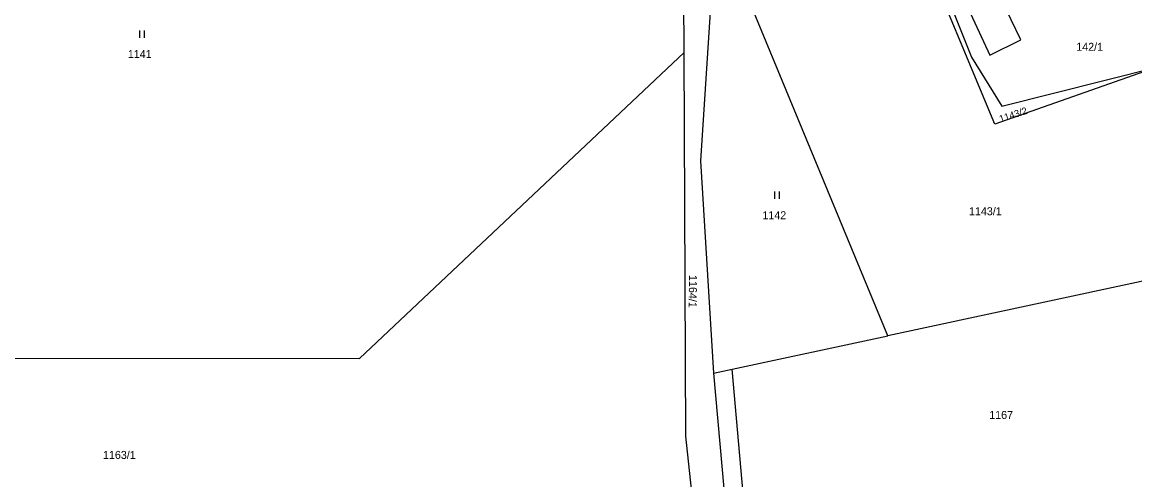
# Model space of a CAD drawing. Extents: x -520431 to -517205, y -1075927 to -1074013.
# Drawn here: x -518114.5 to -517878.1, y -1074275.3 to -1074178 of the extents above; entities that cross this region are included whole.
import ezdxf

# ---------------------------------------------------------------- set-up
doc = ezdxf.new("R2010")
doc.units = 0
for name, color, linetype in [('Hranice parcel', 7, 'Continuous'), ('Parcelní čísla', 7, 'Continuous'), ('Značky kultur', 7, 'Continuous')]:
    doc.layers.add(name, color=color, linetype=linetype)

msp = doc.modelspace()

# ---------------------------------------------------------------- linework, layer by layer
at = {"layer": 'Hranice parcel'}
for p, q in [((-517973.88, -1074184.44), (-517973.95, -1074168.72)), ((-517930.58, -1074244.65), (-517959.87, -1074173.95)), ((-517856.33, -1074228.71), (-517930.58, -1074244.65)), ((-517963.68, -1074251.76), (-517930.58, -1074244.65)), ((-517967.62, -1074252.6), (-517963.68, -1074251.76)), ((-517960.26, -1074290.32), (-517963.68, -1074251.76))]:
    msp.add_line(p, q, dxfattribs=at)
for points in [[(-517873.48, -1074187.52), (-517907.9, -1074199.62), (-517924.26, -1074160.28)], [(-517922.94, -1074159.92), (-517912.81, -1074185.42), (-517906.36, -1074195.86), (-517873.48, -1074187.52)], [(-517916.75, -1074168.08), (-517908.93, -1074185.01), (-517902.33, -1074181.69), (-517910.54, -1074164.66), (-517916.75, -1074168.08)], [(-517961.77, -1074167.62), (-517968.27, -1074174.7), (-517970.39, -1074207.47), (-517967.62, -1074252.6)], [(-518160.31, -1074249.43), (-518042.84, -1074249.49), (-517973.88, -1074184.44)], [(-517969.62, -1074302.45), (-517973.51, -1074266.04), (-517973.88, -1074184.44)], [(-517967.62, -1074252.6), (-517964.09, -1074292.2), (-517962.91, -1074301.55)]]:
    msp.add_lwpolyline(points, dxfattribs=at)
at = {"layer": 'Značky kultur'}
for p, q in [((-518089.51, -1074181.26), (-518089.51, -1074179.76)), ((-518088.51, -1074181.26), (-518088.51, -1074179.76)), ((-517954.62, -1074215.51), (-517954.62, -1074214.01)), ((-517953.62, -1074215.51), (-517953.62, -1074214.01))]:
    msp.add_line(p, q, dxfattribs=at)

# ---------------------------------------------------------------- texts
at = {"layer": 'Parcelní čísla'}
for s, p in [('142/1', (-517890.57, -1074184.05)), ('1141', (-518092.06, -1074185.58)), ('1142', (-517957.25, -1074219.88)), ('1143/1', (-517913.36, -1074219.03)), ('1167', (-517909.06, -1074262.36)), ('1163/1', (-518097.34, -1074270.86))]:
    msp.add_text(s, height=1.7, dxfattribs=at).set_placement(p)
for s, height, rotation, p in [('1143/2', 1.5, 18, (-517906.67, -1074199.3)), ('1164/1', 1.7, 269, (-517972.81, -1074231.74))]:
    msp.add_text(s, height=height, rotation=rotation, dxfattribs=at).set_placement(p)

doc.saveas('drawing.dxf')
